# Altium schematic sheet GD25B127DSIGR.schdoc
size 127 x 101 mm
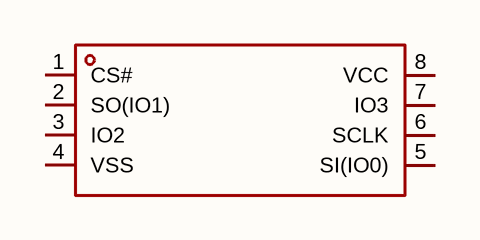
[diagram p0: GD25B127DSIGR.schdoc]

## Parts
U?  gd25b127dsigr  [SOP-8_L5.3-W5.3-P1.27-LS7.9-BL]  (value not drawn)

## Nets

Not connected (* = marked no-connect by the designer): U? 1(CS#) 2(SO(IO1)) 3(IO2) 4(VSS) 5(SI(IO0)) 6(SCLK) 7(IO3) 8(VCC)

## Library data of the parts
U? = gd25b127dsigr: 接口类型:SPI;存储容量:128Mbit;时钟频率(fc):104MHz;; Manufacturer: GigaDevice(兆易创新); AddInBom: yes; ModelId: 72eaeed142424588879d6a198b07ab72; ModelTransform: 207.67675,311.023,0,0,0,0,0,0,0; Interface: SPI; Clock Frequency: 104MHz; Voltage - Supply: 2.7V~3.6V; Standby Supply Current: 20uA; Program / Erase Cycles: 100000次; Page Programming Time (Tpp): 500us; Block Erase Time(tBE): 160ms@(32KB); Data Retention - TDR (Year): 20年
